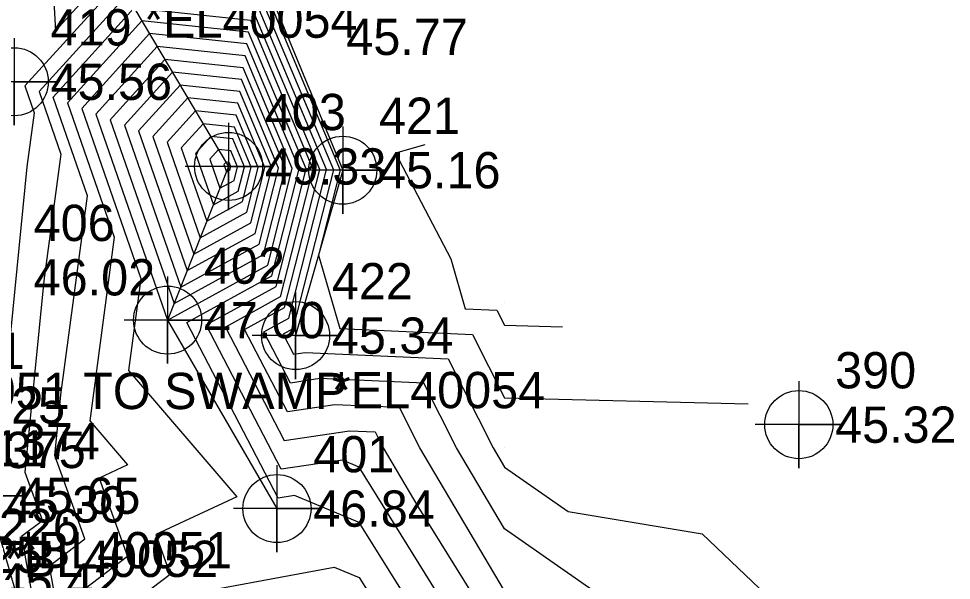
# Model space of a CAD drawing. Extents: x 2090860 to 2091277, y 159470 to 160080.
# Drawn here: x 2091106.5 to 2091170.8, y 159740.9 to 159779.6 of the extents above; entities that cross this region are included whole.
import ezdxf

# ---------------------------------------------------------------- set-up
doc = ezdxf.new("R2010")
doc.units = 0
for name, color, linetype in [('DTM Contours Major', 7, 'Continuous'), ('DTM Contours Minor', 7, 'Continuous'), ('Exist DTM Breakline', 7, 'Continuous'), ('Exist DTM Breakline Cogo Comment', 7, 'Continuous'), ('Exist DTM Breakline Cogo Elevation', 7, 'Continuous'), ('Exist DTM Breakline Cogo Number', 7, 'Continuous'), ('Exist DTM Breakline Cogo Point CELL', 7, 'Continuous'), ('Exist DTM QL2 LIDAR Elevation Point', 7, 'Continuous'), ('Exist DTM Regular Point CELL', 7, 'Continuous'), ('Exist DTM Regular Point Cogo Elevation', 7, 'Continuous'), ('Exist DTM Regular Point Cogo Number', 7, 'Continuous')]:
    doc.layers.add(name, color=color, linetype=linetype)

msp = doc.modelspace()

# ---------------------------------------------------------------- linework, layer by layer
at = {"layer": 'DTM Contours Major'}
for points in [[(2091113.978, 159781.196), (2091107.95, 159774.542), (2091109.45, 159770.226), (2091108.284, 159761.501), (2091106.966, 159748.316), (2091108.177, 159744.971), (2091106.747, 159743.886), (2091107.873, 159737.592), (2091109.304, 159732.696), (2091114.431, 159718.45), (2091115.247, 159716.067), (2091116.563, 159712.414), (2091119.92, 159704.896), (2091128.935, 159685.065), (2091128.953, 159685.024), (2091132.725, 159677.067), (2091142.133, 159658.086), (2091142.373, 159657.575), (2091143.105, 159656.097), (2091147.178, 159648.664), (2091157.027, 159629.517), (2091160.822, 159622.14), (2091162.224, 159619.585), (2091172.872, 159598.824)], [(2091140, 159740.155), (2091134.169, 159750), (2091132.769, 159752.769), (2091128.315, 159752.97), (2091125.049, 159752.485), (2091122.103, 159758.157), (2091124.848, 159759.663), (2091127.273, 159769.18), (2091122.618, 159780.274)], [(2091122.132, 159777.005), (2091116.086, 159777.65), (2091111.867, 159772.994), (2091116.8, 159758.801), (2091123.692, 159762.582), (2091125.389, 159769.241), (2091122.132, 159777.005)], [(2091121.645, 159773.736), (2091118.193, 159774.104), (2091115.784, 159771.446), (2091118.601, 159763.342), (2091122.536, 159765.5), (2091123.505, 159769.303), (2091121.645, 159773.736)], [(2091121.159, 159770.467), (2091120.3, 159770.559), (2091119.701, 159769.897), (2091120.402, 159767.882), (2091121.381, 159768.419), (2091121.622, 159769.365), (2091121.159, 159770.467)], [(2091134.523, 159770.868), (2091132.491, 159770.292), (2091136.303, 159763.03), (2091137.302, 159759.575), (2091139.477, 159759.477), (2091140, 159758.442), (2091143.993, 159758.345)], [(2091120.209, 159740.28), (2091128.27, 159741.774), (2091130, 159741.057), (2091130.655, 159740)]]:
    msp.add_lwpolyline(points, dxfattribs=at)
at = {"layer": 'DTM Contours Minor'}
for points in [[(2091121.095, 159806.882), (2091121.813, 159796.24), (2091121.808, 159795.588), (2091122.568, 159783.548), (2091118.178, 159783.238), (2091122.983, 159782.725), (2091128.686, 159769.134), (2091127.192, 159763.272), (2091128.656, 159758.211), (2091137.8, 159757.8), (2091140, 159753.448), (2091156.79, 159753.04)], [(2091108.829, 159783.167), (2091109.089, 159778.735), (2091112.925, 159782.969)], [(2091113.452, 159782.082), (2091106.971, 159774.929), (2091107.612, 159773.082), (2091107.114, 159769.349), (2091104.896, 159747.166), (2091105.245, 159746.204), (2091104.833, 159745.892), (2091105.157, 159744.081), (2091107.089, 159737.471), (2091114.009, 159718.241), (2091114.505, 159716.794), (2091116.173, 159712.162), (2091118.183, 159707.661), (2091128.555, 159684.843), (2091128.565, 159684.821), (2091130.527, 159680.683), (2091141.814, 159657.91), (2091141.927, 159657.669), (2091142.809, 159655.89), (2091144.716, 159652.41), (2091156.628, 159629.252), (2091161.218, 159620.33), (2091161.719, 159619.417), (2091174.621, 159594.26)], [(2091122.861, 159781.908), (2091128.215, 159769.149), (2091125.426, 159758.204), (2091124.754, 159757.835), (2091125.475, 159756.447), (2091126.274, 159756.566), (2091136.123, 159756.123), (2091139.218, 159750), (2091140, 159748.68), (2091144.395, 159745.605), (2091153.611, 159744.078), (2091164.457, 159733.742), (2091165.521, 159729.312), (2091154.731, 159725.269), (2091156.202, 159720), (2091158.019, 159718.019), (2091160, 159717.218), (2091172.816, 159725.36)], [(2091146.313, 159740), (2091140, 159744.418), (2091136.694, 159750), (2091134.446, 159754.446), (2091127.294, 159754.768), (2091125.262, 159754.466), (2091123.428, 159757.996), (2091125.137, 159758.933), (2091127.744, 159769.165), (2091122.74, 159781.091)], [(2091110.589, 159731.104), (2091108.661, 159741.881), (2091111.109, 159743.738), (2091109.036, 159749.465), (2091109.455, 159753.654), (2091111.287, 159767.37), (2091108.929, 159774.155), (2091114.505, 159780.309), (2091122.497, 159779.456), (2091126.802, 159769.195), (2091124.559, 159760.393), (2091120.777, 159758.318), (2091124.836, 159750.504), (2091129.335, 159751.172), (2091131.093, 159751.093), (2091131.645, 159750), (2091134.034, 159745.966), (2091137.728, 159740)], [(2091122.375, 159778.639), (2091115.032, 159779.423), (2091109.908, 159773.768), (2091113.125, 159764.514), (2091111.434, 159751.856), (2091114.026, 159748.824), (2091112.082, 159747.918), (2091114.042, 159742.505), (2091110.575, 159739.876), (2091113.305, 159724.616), (2091113.735, 159723.145), (2091115.274, 159718.867), (2091116.731, 159714.614), (2091117.342, 159712.916), (2091123.395, 159699.365), (2091129.693, 159685.509), (2091129.729, 159685.429), (2091137.121, 159669.836)], [(2091122.253, 159777.822), (2091115.559, 159778.537), (2091110.888, 159773.381), (2091114.962, 159761.657), (2091114.117, 159755.328), (2091121.559, 159746.623), (2091115.979, 159744.021), (2091116.974, 159741.272), (2091112.489, 159737.87), (2091115.788, 159719.427), (2091116.265, 159719.088), (2091116.021, 159718.127), (2091117.473, 159713.888), (2091117.732, 159713.168), (2091125.132, 159696.599), (2091130.073, 159685.731), (2091130.118, 159685.631), (2091139.319, 159666.221)], [(2091135.37, 159740), (2091130, 159748.673), (2091128.849, 159749.15), (2091124.623, 159748.523), (2091119.451, 159758.479), (2091124.27, 159761.122), (2091126.331, 159769.211), (2091122.375, 159778.639)], [(2091133.012, 159740), (2091130, 159744.865), (2091125.546, 159746.711), (2091124.409, 159746.542), (2091118.126, 159758.64), (2091123.981, 159761.852), (2091125.86, 159769.226), (2091122.253, 159777.822)], [(2091122.01, 159776.187), (2091116.613, 159776.764), (2091112.846, 159772.607), (2091117.25, 159759.936), (2091123.403, 159763.311), (2091124.918, 159769.257), (2091122.01, 159776.187)], [(2091121.889, 159775.37), (2091117.139, 159775.877), (2091113.826, 159772.22), (2091117.7, 159761.071), (2091123.114, 159764.041), (2091124.447, 159769.272), (2091121.889, 159775.37)], [(2091121.767, 159774.553), (2091117.666, 159774.991), (2091114.805, 159771.833), (2091118.151, 159762.206), (2091122.825, 159764.771), (2091123.976, 159769.288), (2091121.767, 159774.553)], [(2091121.524, 159772.919), (2091118.72, 159773.218), (2091116.764, 159771.059), (2091119.051, 159764.477), (2091122.247, 159766.23), (2091123.034, 159769.318), (2091121.524, 159772.919)], [(2091121.402, 159772.101), (2091119.247, 159772.332), (2091117.743, 159770.672), (2091119.501, 159765.612), (2091121.958, 159766.96), (2091122.563, 159769.334), (2091121.402, 159772.101)], [(2091121.281, 159771.284), (2091119.774, 159771.445), (2091118.722, 159770.285), (2091119.952, 159766.747), (2091121.67, 159767.689), (2091122.092, 159769.349), (2091121.281, 159771.284)], [(2091121.037, 159769.65), (2091120.827, 159769.672), (2091120.681, 159769.51), (2091120.852, 159769.017), (2091121.092, 159769.149), (2091121.151, 159769.38), (2091121.037, 159769.65)]]:
    msp.add_lwpolyline(points, dxfattribs=at)
at = {"layer": 'Exist DTM Breakline'}
for p, q in [((2091123.057, 159783.222), (2091128.861, 159769.128)), ((2091128.861, 159769.128), (2091125.613, 159757.731)), ((2091116.8, 159758.801), (2091124.331, 159745.813))]:
    msp.add_line(p, q, dxfattribs=at)
msp.add_lwpolyline([(2091110.781, 159791.407), (2091112.754, 159783.256), (2091120.998, 159769.385), (2091116.8, 159758.801)], dxfattribs=at)
at = {"layer": 'Exist DTM Breakline Cogo Point CELL'}
for points in [[(2091106.238, 159778.219), (2091106.238, 159772.219), (2091106.238, 159775.219), (2091109.238, 159775.219), (2091103.238, 159775.219)], [(2091128.861, 159772.128), (2091128.861, 159766.128), (2091128.861, 159769.128), (2091131.861, 159769.128), (2091125.861, 159769.128)], [(2091125.613, 159760.731), (2091125.613, 159754.731), (2091125.613, 159757.731), (2091128.613, 159757.731), (2091122.613, 159757.731)], [(2091104.06, 159749.702), (2091104.06, 159743.702), (2091104.06, 159746.702), (2091107.06, 159746.702), (2091101.06, 159746.702)]]:
    msp.add_lwpolyline(points, dxfattribs=at)
for centre in [(2091106.238, 159775.219), (2091128.861, 159769.128), (2091125.613, 159757.731)]:
    msp.add_circle(centre, 2.344, dxfattribs=at)
at = {"layer": 'Exist DTM QL2 LIDAR Elevation Point'}
for p, q in [((2091140, 159760), (2091140, 159760)), ((2091110, 159750), (2091110, 159750)), ((2091130, 159750), (2091130, 159750)), ((2091140, 159750), (2091140, 159750))]:
    msp.add_line(p, q, dxfattribs=at)
at = {"layer": 'Exist DTM Regular Point CELL'}
for points in [[(2091120.998, 159772.385), (2091120.998, 159766.385), (2091120.998, 159769.385), (2091123.998, 159769.385), (2091117.998, 159769.385)], [(2091116.8, 159761.801), (2091116.8, 159755.801), (2091116.8, 159758.801), (2091119.8, 159758.801), (2091113.8, 159758.801)], [(2091160.271, 159754.597), (2091160.271, 159748.597), (2091160.271, 159751.597), (2091163.271, 159751.597), (2091157.271, 159751.597)], [(2091124.331, 159748.813), (2091124.331, 159742.813), (2091124.331, 159745.813), (2091127.331, 159745.813), (2091121.331, 159745.813)]]:
    msp.add_lwpolyline(points, dxfattribs=at)
for centre in [(2091120.998, 159769.385), (2091116.8, 159758.801), (2091160.271, 159751.597), (2091124.331, 159745.813)]:
    msp.add_circle(centre, 2.344, dxfattribs=at)

# ---------------------------------------------------------------- texts
at = {"layer": 'Exist DTM Breakline Cogo Comment'}
for s, p in [('*EL40054', (2091115.188, 159778.25)), ('*EL40051 TO SWAMP', (2091095.371, 159752.669)), ('*EL40054', (2091128.113, 159752.731)), ('*BL40051', (2091106.56, 159741.702)), ('*BL40052', (2091105.584, 159741.105))]:
    msp.add_text(s, height=2.5, dxfattribs=at).set_placement(p)
at = {"layer": 'Exist DTM Breakline Cogo Elevation'}
for s, p in [('45.56', (2091108.738, 159773.969)), ('45.16', (2091131.361, 159767.878)), ('45.34', (2091128.113, 159756.481)), ('45.25', (2091101.372, 159751.676)), ('46.11', (2091100.166, 159748.716)), ('45.65', (2091106.56, 159745.452)), ('45.30', (2091105.584, 159744.855)), ('45.42', (2091105.176, 159739.55))]:
    msp.add_text(s, height=2.5, dxfattribs=at).set_placement(p)
at = {"layer": 'Exist DTM Breakline Cogo Number'}
for s, p in [('419', (2091108.738, 159777.719)), ('421', (2091131.361, 159771.628)), ('422', (2091128.113, 159760.231)), ('231', (2091101.372, 159755.426)), ('374', (2091106.56, 159749.202)), ('375', (2091105.584, 159748.605)), ('226', (2091105.176, 159743.3)), ('225', (2091102.622, 159741.375))]:
    msp.add_text(s, height=2.5, dxfattribs=at).set_placement(p)
at = {"layer": 'Exist DTM Regular Point Cogo Elevation'}
for s, p in [('45.77', (2091129.11, 159777.064)), ('49.33', (2091123.498, 159768.135)), ('46.02', (2091107.576, 159760.497)), ('47.00', (2091119.3, 159757.551)), ('45.32', (2091162.771, 159750.347)), ('46.84', (2091126.831, 159744.563))]:
    msp.add_text(s, height=2.5, dxfattribs=at).set_placement(p)
at = {"layer": 'Exist DTM Regular Point Cogo Number'}
for s, p in [('403', (2091123.498, 159771.885)), ('406', (2091107.576, 159764.247)), ('402', (2091119.3, 159761.301)), ('390', (2091162.771, 159754.097)), ('401', (2091126.831, 159748.313))]:
    msp.add_text(s, height=2.5, dxfattribs=at).set_placement(p)

doc.saveas('drawing.dxf')
